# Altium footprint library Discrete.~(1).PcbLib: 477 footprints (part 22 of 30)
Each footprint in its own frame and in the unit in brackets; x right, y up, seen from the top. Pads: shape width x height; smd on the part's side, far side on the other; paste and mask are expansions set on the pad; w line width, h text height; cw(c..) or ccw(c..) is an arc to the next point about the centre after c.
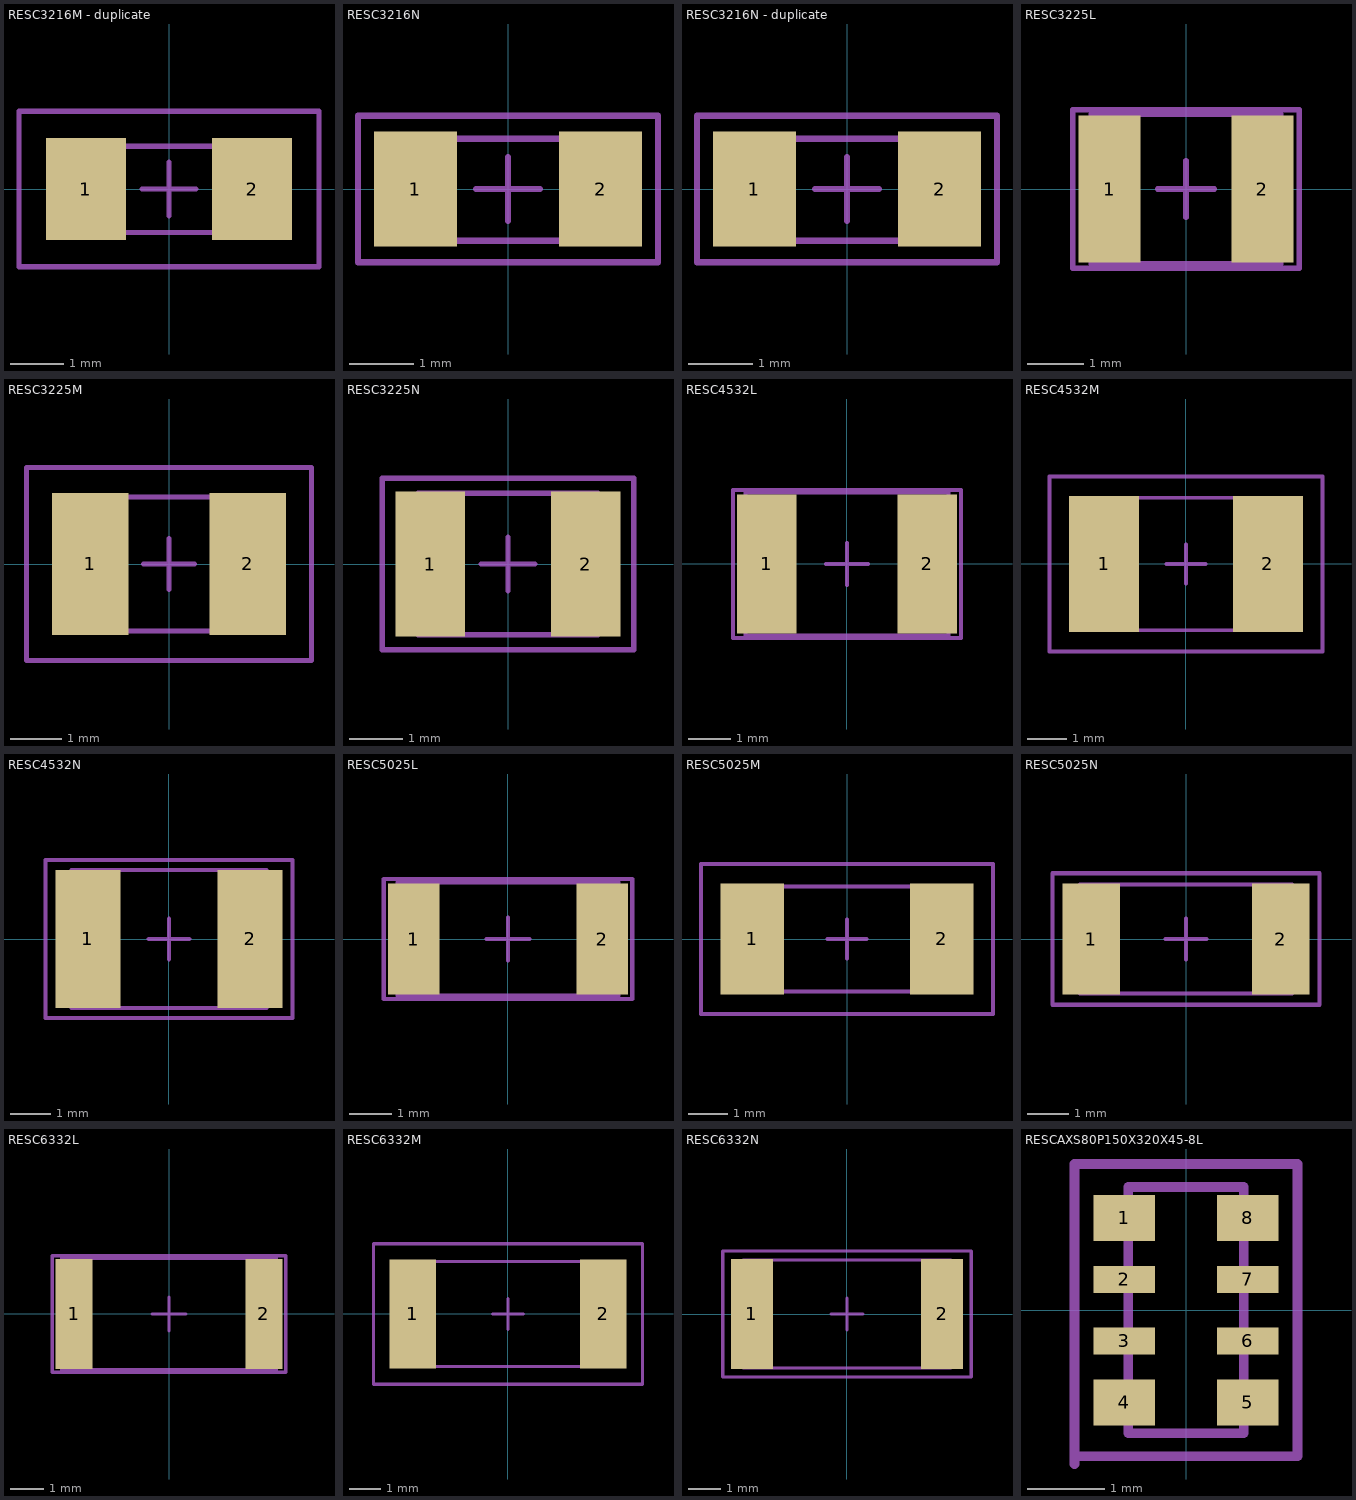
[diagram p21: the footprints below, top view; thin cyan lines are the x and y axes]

## RESC3216M - duplicate [mm] "Chip Resistor, Body 3.2x1.6mm, IPC Low Density"
height 0.71
pads (2):
  rect 1.5x1.9 smd: 1(-1.55,0) 2(1.55,0)
Mechanical 13:
  lines w0.1: -1.6,-0.813 1.601,-0.813 1.601,0.799 0.837,0.799 -1.587,0.799 -1.6,0.8 -1.6,-0.813
Mechanical 15:
  lines w0.1: -0.5,0 0.5,0 ; 0,-0.5 0,0.5 ; -2.8,-1.45 2.8,-1.45 2.8,1.45 -2.8,1.45 -2.8,-1.45
3D body "R 1206.STEP": height 0.55, standoff -0.01, extent -1.6,-0.8 1.6,0.8

## RESC3216N [mm] "Chip Resistor, Body 3.2x1.6mm, IPC Medium Density"
height 0.71
pads (2):
  rect 1.3x1.8 smd: 1(-1.45,0) 2(1.45,0)
Mechanical 13:
  lines w0.1: -1.6,-0.813 -1.6,0.787 1.6,0.787 1.6,-0.813 -1.6,-0.813
Mechanical 15:
  lines w0.1: -0.5,0 0.5,0 ; 0,-0.5 0,0.5 ; -2.35,-1.15 -2.35,1.15 2.35,1.15 2.35,-1.15 -2.35,-1.15
3D body "R 1206.STEP": height 0.55, standoff -0.01, extent -1.6,-0.8 1.6,0.8

## RESC3216N - duplicate [mm] "Chip Resistor, Body 3.2x1.6mm, IPC Medium Density"
height 0.71
pads (2):
  rect 1.3x1.8 smd: 1(-1.45,0) 2(1.45,0)
Mechanical 13:
  lines w0.1: -1.6,-0.813 -1.6,0.787 1.6,0.787 1.6,-0.813 -1.6,-0.813
Mechanical 15:
  lines w0.1: -0.5,0 0.5,0 ; 0,-0.5 0,0.5 ; -2.35,-1.15 -2.35,1.15 2.35,1.15 2.35,-1.15 -2.35,-1.15
3D body "R 1206.STEP": height 0.55, standoff -0.01, extent -1.6,-0.8 1.6,0.8

## RESC3225L [mm] "Chip Resistor, Body 3.2x2.5mm, IPC High Density"
height 0.71
pads (2):
  rect 1.1x2.6 smd: 1(-1.35,0) 2(1.35,0)
Mechanical 13:
  lines w0.1: -1.675,-1.32 -1.675,1.32 1.675,1.32 1.675,-1.32 -1.675,-1.32
Mechanical 15:
  lines w0.1: -0.5,0 0.5,0 ; 0,-0.5 0,0.5 ; -2,-1.4 -2,1.4 2,1.4 2,-1.4 -2,-1.4
3D body "R 1210.STEP": height 0.55, standoff -0.01, extent -1.6,-1.25 1.6,1.25

## RESC3225M [mm] "Chip Resistor, Body 3.2x2.5mm, IPC Low Density"
height 0.71
pads (2):
  rect 1.5x2.8 smd: 1(-1.55,0) 2(1.55,0)
Mechanical 13:
  lines w0.1: -1.675,-1.32 1.675,-1.32 1.675,1.32 -1.675,1.32 -1.675,-1.32
Mechanical 15:
  lines w0.1: -0.5,0 0.5,0 ; 0,-0.5 0,0.5 ; -2.8,-1.9 2.8,-1.9 2.8,1.9 -2.8,1.9 -2.8,-1.9
3D body "R 1210.STEP": height 0.55, standoff -0.01, extent -1.6,-1.25 1.6,1.25

## RESC3225N [mm] "Chip Resistor, Body 3.2x2.5mm, IPC Medium Density"
height 0.71
pads (2):
  rect 1.3x2.7 smd: 1(-1.45,0) 2(1.45,0)
Mechanical 13:
  lines w0.1: -1.675,-1.32 -1.675,1.32 1.675,1.32 1.675,-1.32 -1.675,-1.32
Mechanical 15:
  lines w0.1: -0.5,0 0.5,0 ; 0,-0.5 0,0.5 ; -2.35,-1.6 -2.35,1.6 2.35,1.6 2.35,-1.6 -2.35,-1.6
3D body "R 1210.STEP": height 0.55, standoff -0.01, extent -1.6,-1.25 1.6,1.25

## RESC4532L [mm] "Chip Resistor, Body 4.5x3.2mm, IPC High Density"
height 0.71
pads (2):
  rect 1.4x3.3 smd: 1(-1.9,0) 2(1.9,0)
Mechanical 13:
  lines w0.1: -2.4,-1.7 -2.4,1.7 2.4,1.7 2.4,-1.7 -2.4,-1.7
Mechanical 15:
  lines w0.1: -0.5,0 0.5,0 ; 0,-0.5 0,0.5 ; -2.7,-1.75 -2.7,1.75 2.7,1.75 2.7,-1.75 -2.7,-1.75
3D body: height 0.71, standoff 0, extent -2.4,-1.7 2.4,1.7

## RESC4532M [mm] "Chip Resistor, Body 4.5x3.2mm, IPC Low Density"
height 0.71
pads (2):
  rect 1.8x3.5 smd: 1(-2.1,0) 2(2.1,0)
Mechanical 13:
  lines w0.1: -2.4,-1.7 2.4,-1.7 2.4,1.7 -2.4,1.7 -2.4,-1.7
Mechanical 15:
  lines w0.1: -0.5,0 0.5,0 ; 0,-0.5 0,0.5 ; -3.5,-2.25 3.5,-2.25 3.5,2.25 -3.5,2.25 -3.5,-2.25
3D body: height 0.71, standoff 0, extent -2.4,-1.7 2.4,1.7

## RESC4532N [mm] "Chip Resistor, Body 4.5x3.2mm, IPC Medium Density"
height 0.71
pads (2):
  rect 1.6x3.4 smd: 1(-2,0) 2(2,0)
Mechanical 13:
  lines w0.1: -2.4,-1.7 -2.4,1.7 2.4,1.7 2.4,-1.7 -2.4,-1.7
Mechanical 15:
  lines w0.1: -0.5,0 0.5,0 ; 0,-0.5 0,0.5 ; -3.05,-1.95 -3.05,1.95 3.05,1.95 3.05,-1.95 -3.05,-1.95
3D body: height 0.71, standoff 0, extent -2.4,-1.7 2.4,1.7

## RESC5025L [mm] "Chip Resistor, Body 5.0x2.5mm, IPC High Density"
height 0.71
pads (2):
  rect 1.2x2.6 smd: 1(-2.2,0) 2(2.2,0)
Mechanical 13:
  lines w0.1: -2.575,-1.325 -2.575,1.325 2.575,1.325 2.575,-1.325 -2.575,-1.325
Mechanical 15:
  lines w0.1: -0.5,0 0.5,0 ; 0,-0.5 0,0.5 ; -2.9,-1.4 -2.9,1.4 2.9,1.4 2.9,-1.4 -2.9,-1.4
3D body "R 2010.STEP": height 0.55, standoff -0.01, extent -2.5,-1.25 2.5,1.25

## RESC5025M [mm] "Chip Resistor, Body 5.0x2.5mm, IPC Low Density"
height 0.71
pads (2):
  rect 1.6x2.8 smd: 1(-2.4,0) 2(2.4,0)
Mechanical 13:
  lines w0.1: -2.575,-1.325 -2.575,1.325 2.575,1.325 2.575,-1.325 -2.575,-1.325
Mechanical 15:
  lines w0.1: -0.5,0 0.5,0 ; 0,-0.5 0,0.5 ; -3.7,-1.9 -3.7,1.9 3.7,1.9 3.7,-1.9 -3.7,-1.9
3D body "R 2010.STEP": height 0.55, standoff -0.01, extent -2.5,-1.25 2.5,1.25

## RESC5025N [mm] "Chip Resistor, Body 5.0x2.5mm, IPC Medium Density"
height 0.71
pads (2):
  rect 1.4x2.7 smd: 1(-2.3,0) 2(2.3,0)
Mechanical 13:
  lines w0.1: -2.575,-1.325 2.575,-1.325 2.575,1.325 -2.575,1.325 -2.575,-1.325
Mechanical 15:
  lines w0.1: -0.5,0 0.5,0 ; 0,-0.5 0,0.5 ; -3.25,-1.6 3.25,-1.6 3.25,1.6 -3.25,1.6 -3.25,-1.6
3D body "R 2010.STEP": height 0.55, standoff -0.01, extent -2.5,-1.25 2.5,1.25

## RESC6332L [mm] "Chip Resistor, Body 6.3x3.2mm, IPC High Density"
height 0.71
pads (2):
  rect 1.1x3.3 smd: 1(-2.85,0) 2(2.85,0)
Mechanical 13:
  lines w0.1: -3.225,-1.675 -3.225,1.675 3.225,1.675 3.225,-1.675 -3.225,-1.675
Mechanical 15:
  lines w0.1: -0.5,0 0.5,0 ; 0,-0.5 0,0.5 ; -3.5,-1.75 -3.5,1.75 3.5,1.75 3.5,-1.75 -3.5,-1.75
3D body "R 2512.STEP": height 0.55, standoff -0.02, extent -3.2,-1.6 3.2,1.6

## RESC6332M [mm] "Chip Resistor, Body 6.3x3.2mm, IPC Low Density"
height 0.71
pads (2):
  rect 1.5x3.5 smd: 1(-3.05,0) 2(3.05,0)
Mechanical 13:
  lines w0.1: -3.225,-1.675 3.225,-1.675 3.225,1.675 -3.225,1.675 -3.225,-1.675
Mechanical 15:
  lines w0.1: -0.5,0 0.5,0 ; 0,-0.5 0,0.5 ; -4.3,-2.25 4.3,-2.25 4.3,2.25 -4.3,2.25 -4.3,-2.25
3D body "R 2512.STEP": height 0.55, standoff -0.02, extent -3.2,-1.6 3.2,1.6

## RESC6332N [mm] "Chip Resistor, Body 6.3x3.2mm, IPC Medium Density"
height 0.71
pads (2):
  rect 1.3x3.4 smd: 1(-2.95,0) 2(2.95,0)
Mechanical 13:
  lines w0.1: -3.225,-1.675 -3.225,1.675 3.225,1.675 3.225,-1.675 -3.225,-1.675
Mechanical 15:
  lines w0.1: -0.5,0 0.5,0 ; 0,-0.5 0,0.5 ; -3.85,-1.95 -3.85,1.95 3.85,1.95 3.85,-1.95 -3.85,-1.95
3D body "R 2512.STEP": height 0.55, standoff -0.02, extent -3.2,-1.6 3.2,1.6

## RESCAXS80P150X320X45-8L [mm] "Resistor Array 0603X4 S-VERSION"
pads (8):
  rect 0.8x0.6 smd mask+0: 1(-0.8,1.2) 4(-0.8,-1.2) 5(0.8,-1.2) 8(0.8,1.2)
  rect 0.8x0.35 smd mask+0: 2(-0.8,0.4) 3(-0.8,-0.4) 6(0.8,-0.4) 7(0.8,0.4)
Mechanical 13:
  lines w0.127: -0.75,-1.6 0.75,-1.6 0.75,1.6 -0.75,1.6 -0.75,-1.6
Mechanical 15:
  lines w0.127: -1.45,-2 -1.45,1.9 1.45,1.9 1.45,-1.9 -1.45,-1.9
3D body "User Library-TC164.STEP": height 0.55, standoff 0, extent -0.8,-1.6 0.8,1.6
